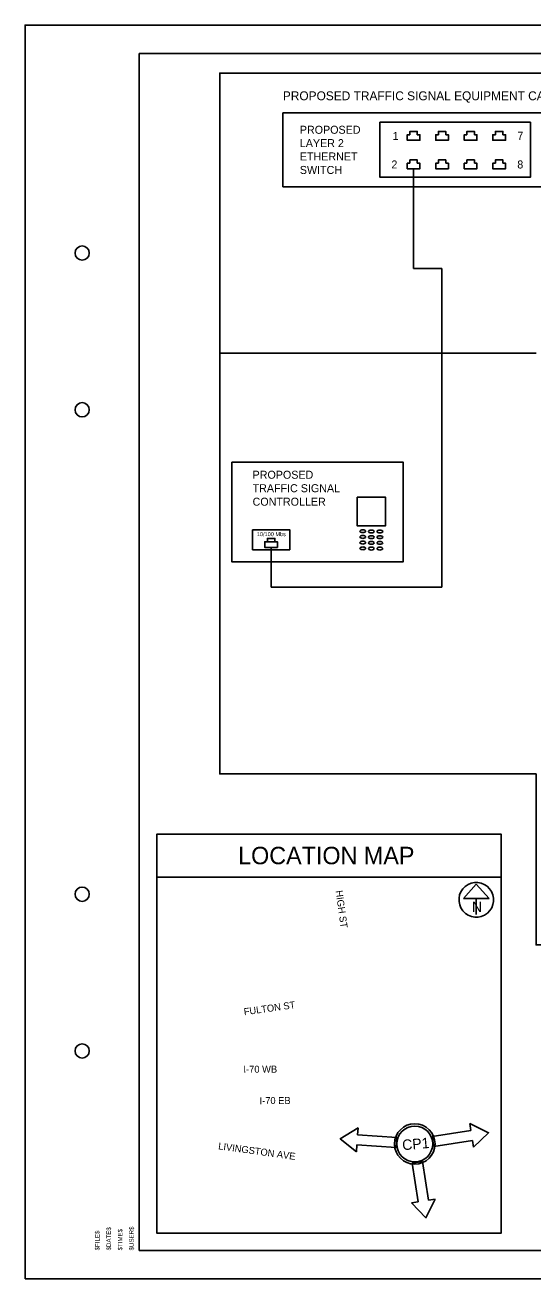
# Model space of a CAD drawing. Extents: x 1805893 to 1833564, y 708898 to 716199.
# Drawn here: x 1831322.5 to 1831500.5, y 713757.9 to 714197.9 of the extents above; entities that cross this region are included whole.
import ezdxf

# ---------------------------------------------------------------- set-up
doc = ezdxf.new("R2010")
doc.units = 0
for name, color, linetype in [('BR_P_Sub_Hidden', 7, 'Continuous'), ('SH_Border', 7, 'Continuous'), ('SH_Cut_Line', 7, 'Continuous'), ('SH_Data', 7, 'Continuous'), ('SH_Text', 7, 'Continuous'), ('UT_X_Misc_Cells', 7, 'Continuous')]:
    doc.layers.add(name, color=color, linetype=linetype)

msp = doc.modelspace()

# ---------------------------------------------------------------- linework, layer by layer
at = {"layer": 'BR_P_Sub_Hidden'}
msp.add_line((1831501.65, 714082.72), (1831390.73, 714082.72), dxfattribs=at)
msp.add_lwpolyline([(1831501.65, 713935.11), (1831390.73, 713935.11), (1831390.73, 714181.08), (1831814.91, 714181.08), (1831814.91, 714105.3), (1831725.63, 714105.3), (1831725.63, 713875.12), (1831501.65, 713875.12)], close=True, dxfattribs=at)
at = {"layer": 'SH_Border'}
msp.add_lwpolyline([(1831362.49, 714187.91), (1831992.49, 714187.91), (1831992.49, 713767.91), (1831362.49, 713767.91)], close=True, dxfattribs=at)
for centre in [(1831342.49, 714117.91), (1831342.49, 714062.91), (1831342.49, 713892.91), (1831342.49, 713837.91)]:
    msp.add_circle(centre, 2.5, dxfattribs=at)
at = {"layer": 'SH_Cut_Line'}
msp.add_lwpolyline([(1831322.49, 713757.91), (1832002.49, 713757.91), (1832002.49, 714197.91), (1831322.49, 714197.91)], close=True, dxfattribs=at)
at = {"layer": 'SH_Data'}
for p, q in [((1831458.71, 714147.47), (1831458.71, 714112.47)), ((1831458.71, 714112.47), (1831468.63, 714112.47)), ((1831468.63, 714112.47), (1831468.63, 714000.61)), ((1831408.76, 714014.62), (1831408.76, 714000.61)), ((1831408.76, 714000.61), (1831468.63, 714000.61))]:
    msp.add_line(p, q, dxfattribs=at)
for points in [[(1831412.87, 714167.16), (1831542.87, 714167.16), (1831542.87, 714141.16), (1831412.87, 714141.16)], [(1831446.88, 714163.8), (1831499.69, 714163.8), (1831499.69, 714144.53), (1831446.88, 714144.53)], [(1831395.03, 714044.55), (1831455.03, 714044.55), (1831455.03, 714009.55), (1831395.03, 714009.55)], [(1831438.89, 714032.2), (1831448.89, 714032.2), (1831448.89, 714022.2), (1831438.89, 714022.2)], [(1831402.26, 714020.79), (1831415.26, 714020.79), (1831415.26, 714013.79), (1831402.26, 714013.79)], [(1831406.54, 714016.6), (1831410.98, 714016.6), (1831410.98, 714014.62), (1831406.54, 714014.62)], [(1831407.46, 714017.77), (1831410.06, 714017.77), (1831410.06, 714016.6), (1831407.46, 714016.6)], [(1831489.36, 713914.04), (1831368.72, 713914.04), (1831368.72, 713898.93), (1831489.36, 713898.93)], [(1831489.36, 713898.93), (1831368.72, 713898.93), (1831368.72, 713914.04), (1831489.36, 713914.04)], [(1831489.36, 713898.93), (1831489.36, 713773.91), (1831368.72, 713773.91), (1831368.72, 713898.93)], [(1831489.36, 713898.93), (1831489.36, 713773.91), (1831368.72, 713773.91), (1831368.72, 713898.93)], [(1831489.36, 713898.93), (1831489.36, 713773.91), (1831368.72, 713773.91), (1831368.72, 713898.93)]]:
    msp.add_lwpolyline(points, close=True, dxfattribs=at)
for points in [[(1831457.41, 714159.45), (1831457.41, 714160.62), (1831460.01, 714160.62), (1831460.01, 714159.45)], [(1831467.41, 714159.45), (1831467.41, 714160.62), (1831470.01, 714160.62), (1831470.01, 714159.45)], [(1831477.41, 714159.45), (1831477.41, 714160.62), (1831480.01, 714160.62), (1831480.01, 714159.45)], [(1831487.41, 714159.45), (1831487.41, 714160.62), (1831490.01, 714160.62), (1831490.01, 714159.45)], [(1831460.01, 714159.45), (1831460.94, 714159.45), (1831460.94, 714157.47), (1831456.49, 714157.47), (1831456.49, 714159.45), (1831457.41, 714159.45)], [(1831470.01, 714159.45), (1831470.94, 714159.45), (1831470.94, 714157.47), (1831466.49, 714157.47), (1831466.49, 714159.45), (1831467.41, 714159.45)], [(1831480.01, 714159.45), (1831480.94, 714159.45), (1831480.94, 714157.47), (1831476.49, 714157.47), (1831476.49, 714159.45), (1831477.41, 714159.45)], [(1831490.01, 714159.45), (1831490.94, 714159.45), (1831490.94, 714157.47), (1831486.49, 714157.47), (1831486.49, 714159.45), (1831487.41, 714159.45)], [(1831460.01, 714149.45), (1831460.94, 714149.45), (1831460.94, 714147.47), (1831456.49, 714147.47), (1831456.49, 714149.45), (1831457.41, 714149.45)], [(1831457.41, 714149.45), (1831457.41, 714150.62), (1831460.01, 714150.62), (1831460.01, 714149.45)], [(1831470.01, 714149.45), (1831470.94, 714149.45), (1831470.94, 714147.47), (1831466.49, 714147.47), (1831466.49, 714149.45), (1831467.41, 714149.45)], [(1831467.41, 714149.45), (1831467.41, 714150.62), (1831470.01, 714150.62), (1831470.01, 714149.45)], [(1831480.01, 714149.45), (1831480.94, 714149.45), (1831480.94, 714147.47), (1831476.49, 714147.47), (1831476.49, 714149.45), (1831477.41, 714149.45)], [(1831477.41, 714149.45), (1831477.41, 714150.62), (1831480.01, 714150.62), (1831480.01, 714149.45)], [(1831490.01, 714149.45), (1831490.94, 714149.45), (1831490.94, 714147.47), (1831486.49, 714147.47), (1831486.49, 714149.45), (1831487.41, 714149.45)], [(1831487.41, 714149.45), (1831487.41, 714150.62), (1831490.01, 714150.62), (1831490.01, 714149.45)], [(1831410.06, 714016.6), (1831407.46, 714016.6), (1831406.54, 714016.6), (1831406.54, 714014.62), (1831410.98, 714014.62), (1831410.98, 714016.6), (1831410.06, 714016.6)], [(1831407.46, 714016.6), (1831410.06, 714016.6), (1831410.06, 714017.77), (1831407.46, 714017.77), (1831407.46, 714016.6)]]:
    msp.add_lwpolyline(points, dxfattribs=at)
for centre in [(1831440.9, 714020.29), (1831443.89, 714020.2), (1831446.89, 714020.2), (1831440.9, 714018.29), (1831440.9, 714016.29), (1831440.9, 714014.29), (1831443.89, 714018.2), (1831443.89, 714016.2), (1831443.89, 714014.2), (1831446.89, 714018.2), (1831446.89, 714016.2), (1831446.89, 714014.2)]:
    msp.add_ellipse(centre, major_axis=(1, 0), ratio=0.5, dxfattribs=at)
at = {"layer": 'SH_Text'}
for p, q in [((1831480.69, 713896.42), (1831476.18, 713891.42)), ((1831485.19, 713891.42), (1831480.69, 713896.42)), ((1831476.18, 713891.42), (1831485.19, 713891.42)), ((1831480.69, 713891.42), (1831480.69, 713885.76)), ((1831478.81, 713810.04), (1831478.44, 713812.41)), ((1831439.26, 713810.91), (1831439.1, 713808.51)), ((1831439.1, 713808.51), (1831452.8, 713807.58)), ((1831465.23, 713807.94), (1831478.81, 713810.04)), ((1831465.79, 713804.38), (1831465.23, 713807.94)), ((1831438.85, 713804.92), (1831438.69, 713802.53)), ((1831452.56, 713803.99), (1831438.85, 713804.92)), ((1831452.8, 713807.58), (1831452.56, 713803.99)), ((1831479.36, 713806.48), (1831465.79, 713804.38)), ((1831479.73, 713804.11), (1831479.36, 713806.48)), ((1831458.24, 713798.58), (1831461.79, 713799.14)), ((1831461.79, 713799.14), (1831463.9, 713785.56)), ((1831460.34, 713785.01), (1831458.24, 713798.58)), ((1831463.9, 713785.56), (1831466.27, 713785.93)), ((1831457.97, 713784.64), (1831460.34, 713785.01))]:
    msp.add_line(p, q, dxfattribs=at)
for points in [[(1831478.44, 713812.41), (1831485.01, 713809.18), (1831479.73, 713804.11)], [(1831438.69, 713802.53), (1831432.99, 713807.12), (1831439.26, 713810.91)], [(1831466.27, 713785.93), (1831463.04, 713779.36), (1831457.97, 713784.64)]]:
    msp.add_lwpolyline(points, dxfattribs=at)
for radius in [7.11, 6.31]:
    msp.add_circle((1831459.11, 713805.26), radius, dxfattribs=at)
msp.add_arc((1831480.69, 713890.95), 6.08, 129.7798, 129.7633, dxfattribs=at)

# ---------------------------------------------------------------- texts
at = {"layer": 'SH_Data'}
for s, height, p in [('PROPOSED TRAFFIC SIGNAL EQUIPMENT CABINET', 3.1201, (1831412.87, 714171.53)), ('PROPOSED ', 2.808, (1831418.82, 714159.77)), ('1', 2.81, (1831451.34, 714157.59)), ('7', 2.81, (1831495.09, 714157.64)), ('LAYER 2 ', 2.808, (1831418.82, 714155.08)), ('ETHERNET ', 2.808, (1831418.82, 714150.4)), ('SWITCH', 2.808, (1831418.82, 714145.67)), ('2', 2.81, (1831450.93, 714147.59)), ('8', 2.81, (1831495.07, 714147.59)), ('PROPOSED', 2.808, (1831402.26, 714038.71)), ('TRAFFIC SIGNAL ', 2.8081, (1831402.26, 714033.98)), ('CONTROLLER', 2.808, (1831402.26, 714029.25)), ('10/100 Mbs', 1.404, (1831403.78, 714018.56)), ('LOCATION MAP', 6.1191, (1831397.18, 713903.43))]:
    msp.add_text(s, height=height, dxfattribs=at).set_placement(p)
at = {"layer": 'SH_Text'}
for s, height, rotation, p in [('HIGH ST', 2.448, 278.061, (1831431.33, 713894.08)), ('N', 3.66, 360, (1831479.17, 713886.68)), ('FULTON ST', 2.448, 8.061, (1831399.34, 713850.41)), ('I-70 WB', 2.448, 0.3445, (1831399.05, 713830.24)), ('I-70 EB', 2.448, 0.3445, (1831404.69, 713819.23)), ('LIVINGSTON AVE', 2.4477, 352.086, (1831390.1, 713803.41)), ('CP1', 3.671, 5, (1831454.88, 713803.04))]:
    msp.add_text(s, height=height, rotation=rotation, dxfattribs=at).set_placement(p)
at = {"layer": 'UT_X_Misc_Cells'}
for s, p in [('$FILE$', (1831348.59, 713767.91)), ('$DATE$', (1831352.59, 713767.91)), ('$TIME$', (1831356.59, 713767.91)), ('$USER$', (1831360.59, 713767.91))]:
    msp.add_text(s, height=1.56, rotation=90, dxfattribs=at).set_placement(p)

doc.saveas('drawing.dxf')
